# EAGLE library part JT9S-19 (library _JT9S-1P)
Joystick Potentiometer 10k
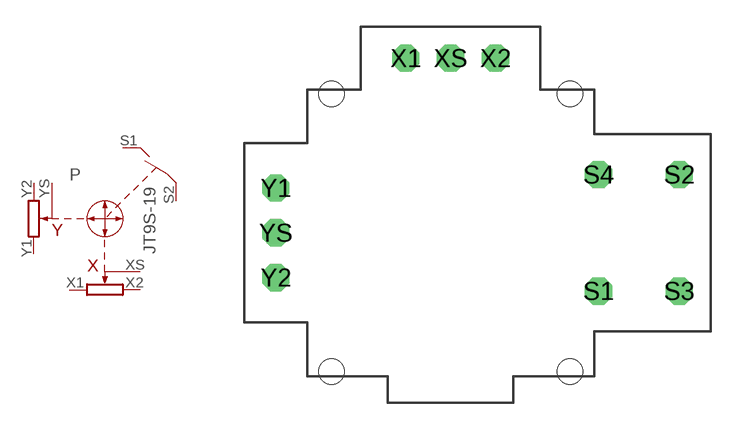
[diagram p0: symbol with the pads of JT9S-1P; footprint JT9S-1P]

Designator prefix P

## JT9S-19  [JT9S-1P]
S1  S1  pas
S2  S2  pas
X1  X1  pas
X2  X2  pas
XS  XS  pas
Y1  Y1  pas
Y2  Y2  pas
YS  YS  pas

## Footprint JT9S-1P (pad centres in mm)
drill 1.016 octagon: S1 8.25,-3.25; S2 12.75,3.25; S3 12.75,-3.25; S4 8.25,3.25; X1 -2.5,9.75; X2 2.5,9.75; XS 0,9.75; Y1 -9.75,2.5; Y2 -9.75,-2.5; YS -9.75,0
hole 1.422 at -6.65,7.75
hole 1.422 at 6.65,7.75
hole 1.422 at 6.65,-7.75
hole 1.422 at -6.65,-7.75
